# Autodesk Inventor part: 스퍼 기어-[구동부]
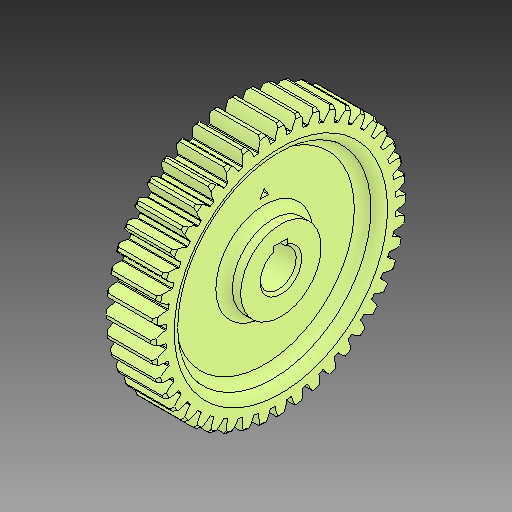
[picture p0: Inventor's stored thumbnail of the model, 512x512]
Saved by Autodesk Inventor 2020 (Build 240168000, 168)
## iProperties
Created: 2025-02
Part Number: 스퍼 기어-[구동부]
Material: 일반
Document SubType Name: Modeling
Designer: 1강의실14
Density: 1 g/cm^3
Appearance: 기본값
Sending System: Autodesk Inventor 2025
Preprocessor: ST-DEVELOPER v20
Author: jhkim
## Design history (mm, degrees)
feature "솔리드1"
node "솔리드2"
